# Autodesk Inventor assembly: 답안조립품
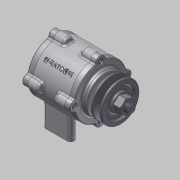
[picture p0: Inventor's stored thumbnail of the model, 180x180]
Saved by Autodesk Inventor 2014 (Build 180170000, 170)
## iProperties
Created: 2015-03
Part Number: 답안조립품
Document SubType Name: Assembly
Designer: MYHOME
Author: MYHOME
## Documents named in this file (11)
- C:\Documents and Settings\MYHOME\바탕 화면\450306V1027\답안조립품.iam
- C:\Documents and Settings\MYHOME\바탕 화면\450306V1027\본체.ipt
- C:\Documents and Settings\MYHOME\바탕 화면\450306V1027\커버.ipt
- C:\Documents and Settings\MYHOME\바탕 화면\450306V1027\커버2.ipt
- C:\Documents and Settings\MYHOME\바탕 화면\450306V1027\M 4 x 12.ipt
- C:\Documents and Settings\MYHOME\바탕 화면\450306V1027\오일실.ipt
- C:\Documents and Settings\MYHOME\바탕 화면\450306V1027\베어링 6204.ipt
- C:\Documents and Settings\MYHOME\바탕 화면\450306V1027\축.ipt
- C:\Documents and Settings\MYHOME\바탕 화면\450306V1027\키(4 x 4 x 12).ipt
- C:\Documents and Settings\MYHOME\바탕 화면\450306V1027\V벨트풀리.ipt
- C:\Documents and Settings\MYHOME\바탕 화면\450306V1027\너트 M12x1.25.ipt
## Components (14 placed, 6 different names)
1. KS B 2804 D D - 20 32 8:1
2. KS B 2023 6204 - 20 x 47 x 14:1 — 각도:1
3. KS B 2023 6204 - 20 x 47 x 14:2 — 각도:2
4. KS B 1311 (I) 4 x 4 x 12:1
5. 그루브 풀리1:1
6. KS B 1012 클래스 1 일반 - 미터 M12x1.25:1
7. KS B 1003 - 미터 M 4 x 12:2
8. KS B 1003 - 미터 M 4 x 12:3
9. KS B 1003 - 미터 M 4 x 12:4
10. KS B 1003 - 미터 M 4 x 12:5
11. KS B 1003 - 미터 M 4 x 12:1
12. KS B 1003 - 미터 M 4 x 12:6
13. KS B 1003 - 미터 M 4 x 12:7
14. KS B 1003 - 미터 M 4 x 12:8
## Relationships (2: Angle 2)
- 각도:1 [Angle]: KS B 2023 6204 - 20 x 47 x 14:1
- 각도:2 [Angle]: KS B 2023 6204 - 20 x 47 x 14:2
